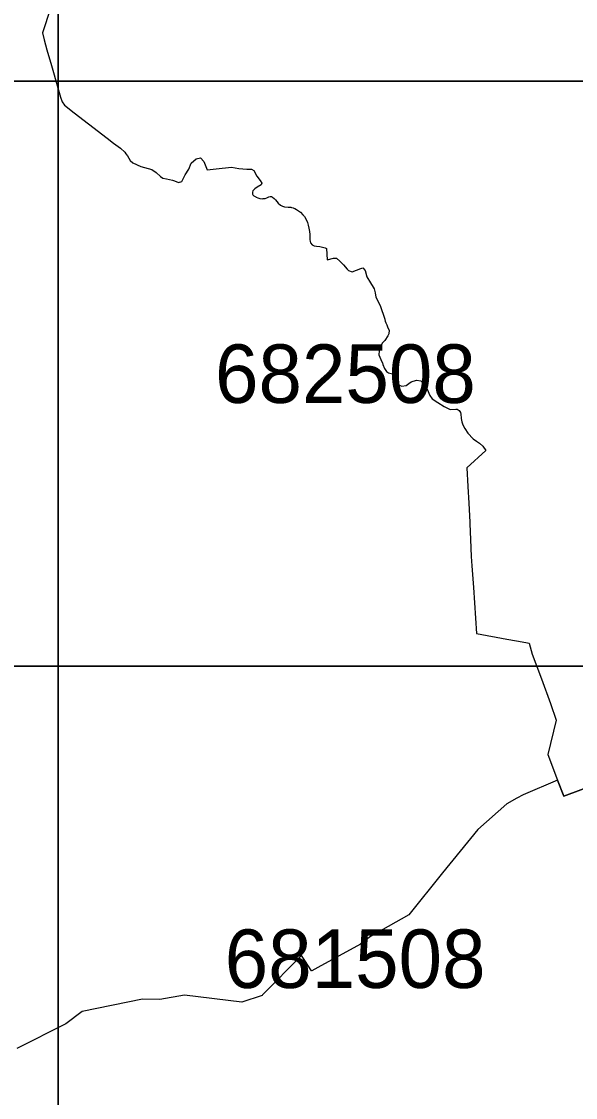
# Model space of a CAD drawing. Extents: x 25485000 to 25520000, y 6656775 to 6690000.
# Drawn here: x 25507937 to 25508885, y 6681263 to 6683102 of the extents above; entities that cross this region are included whole.
import ezdxf

# ---------------------------------------------------------------- set-up
doc = ezdxf.new("R2010")
doc.units = 0
doc.layers.add('Level 63', color=7, linetype='Continuous')

msp = doc.modelspace()

# ---------------------------------------------------------------- linework, layer by layer
at = {"layer": 'Level 63'}
for points in [[(25507000, 6683000), (25508000, 6683000), (25508000, 6684000), (25507000, 6684000)], [(25508000, 6683000), (25509000, 6683000), (25509000, 6684000), (25508000, 6684000)], [(25507000, 6682000), (25508000, 6682000), (25508000, 6683000), (25507000, 6683000)], [(25508000, 6682000), (25509000, 6682000), (25509000, 6683000), (25508000, 6683000)], [(25507000, 6681000), (25508000, 6681000), (25508000, 6682000), (25507000, 6682000)], [(25508000, 6681000), (25509000, 6681000), (25509000, 6682000), (25508000, 6682000)]]:
    msp.add_lwpolyline(points, close=True, dxfattribs=at)
for points in [[(25507986.9, 6683124.1), (25507973.1, 6683082.6), (25507976.3, 6683070.6), (25507981, 6683053.8), (25507988.6, 6683027), (25507999.4, 6682988.8), (25508004, 6682972.4), (25508007, 6682964.7), (25508011.2, 6682959), (25508027.8, 6682945.8), (25508052, 6682927.3), (25508083.9, 6682902.4), (25508094.7, 6682894.3), (25508106.7, 6682885.3), (25508114, 6682878.7), (25508116.2, 6682875.9), (25508119, 6682872.4), (25508123.5, 6682864.4), (25508127.8, 6682860.2), (25508141.6, 6682854.4), (25508160.6, 6682848.8), (25508167.8, 6682843.8), (25508175.1, 6682837.3), (25508179.5, 6682834.4), (25508185.7, 6682833.2), (25508195.8, 6682830.9), (25508199.4, 6682829.4), (25508205.8, 6682826.8), (25508211.5, 6682828.6), (25508217.5, 6682840), (25508223.9, 6682849.3), (25508227.9, 6682860), (25508236.5, 6682867.5), (25508243.4, 6682869.1), (25508249.6, 6682862.5), (25508255, 6682848.6), (25508270.6, 6682849.9), (25508296.7, 6682853), (25508309.4, 6682850.8), (25508323.2, 6682849.6), (25508330.9, 6682849.4), (25508334.8, 6682847.1), (25508340.3, 6682837.4), (25508345.6, 6682830.2), (25508348.8, 6682825.9), (25508347.3, 6682822.8), (25508340.7, 6682818.6), (25508336.5, 6682816), (25508333.3, 6682812.3), (25508332.6, 6682810), (25508332.4, 6682808.1), (25508332.6, 6682806.7), (25508333, 6682805.7), (25508335, 6682804), (25508338.3, 6682802.1), (25508339.1, 6682801.6), (25508342, 6682800.3), (25508345.4, 6682799.4), (25508350.2, 6682799.1), (25508350.9, 6682799.2), (25508354.2, 6682799.4), (25508357.3, 6682800.5), (25508360.8, 6682802.4), (25508362.9, 6682803), (25508365.1, 6682802.7), (25508367.1, 6682801.9), (25508369.7, 6682799.6), (25508372.1, 6682796.9), (25508374.1, 6682794.3), (25508376.8, 6682791.2), (25508380.3, 6682788.1), (25508383.9, 6682786.1), (25508387.5, 6682785.4), (25508393.6, 6682784.6), (25508394.9, 6682784.6), (25508398.2, 6682784.5), (25508399.6, 6682784.1), (25508402.2, 6682783.5), (25508403.2, 6682783.1), (25508405.1, 6682782.2), (25508408.1, 6682780.6), (25508411.5, 6682778.5), (25508414.6, 6682776.1), (25508419, 6682771.7), (25508421.7, 6682768.4), (25508424.4, 6682763.3), (25508426.5, 6682758.5), (25508428, 6682753.7), (25508429.2, 6682748.5), (25508430.1, 6682743.2), (25508430.7, 6682737.9), (25508430.9, 6682729.2), (25508431.2, 6682726.2), (25508431.8, 6682723.5), (25508434.9, 6682720.3), (25508438.2, 6682718.6), (25508441.9, 6682717.8), (25508447.8, 6682717.2), (25508457, 6682714.9), (25508459.1, 6682713.9), (25508460.4, 6682694.7), (25508471.3, 6682697.3), (25508476.2, 6682697.6), (25508482.2, 6682692.5), (25508488.1, 6682686), (25508494.6, 6682678.9), (25508496.8, 6682676.5), (25508503.2, 6682674.3), (25508518.2, 6682680), (25508521.6, 6682680.8), (25508525.5, 6682676.5), (25508528.2, 6682665.8), (25508534.7, 6682655), (25508539.1, 6682647.8), (25508540.7, 6682645.1), (25508542.7, 6682638.2), (25508543.5, 6682631), (25508551.1, 6682616.3), (25508558.8, 6682593.1), (25508559, 6682592.3), (25508559.5, 6682590.9), (25508559.9, 6682590), (25508561, 6682587), (25508562.3, 6682583.3), (25508564.3, 6682578.1), (25508566.4, 6682574.4), (25508566, 6682568.1), (25508564.2, 6682564.6), (25508558.8, 6682556.9), (25508554.6, 6682552.1), (25508549.3, 6682539), (25508548.8, 6682532.1), (25508552.2, 6682524.4), (25508554.6, 6682519.2), (25508555, 6682518.3), (25508555.8, 6682515.9), (25508558.3, 6682508.9), (25508561.7, 6682504), (25508565.4, 6682501.2), (25508572.3, 6682500), (25508574.4, 6682498.1), (25508580, 6682484), (25508582.5, 6682481.1), (25508588.2, 6682478.8), (25508595.3, 6682480), (25508599.9, 6682483), (25508604.1, 6682485.9), (25508613.4, 6682488.7), (25508620.5, 6682487.9), (25508626.1, 6682482.8), (25508631.5, 6682473.6), (25508635.9, 6682462.5), (25508639.9, 6682456.9), (25508650, 6682450.7), (25508660.8, 6682444.1), (25508671.1, 6682438.7), (25508680.6, 6682439.5), (25508683.1, 6682439.6), (25508686.5, 6682436.8), (25508688.5, 6682433.4), (25508688.9, 6682430.9), (25508689.2, 6682429.2), (25508689.6, 6682425.9), (25508689.9, 6682423.2), (25508690.7, 6682417.7), (25508692.6, 6682412.4), (25508695.9, 6682406.4), (25508701.3, 6682398.3), (25508710.1, 6682388.4), (25508715.7, 6682384.6), (25508720.9, 6682381.5), (25508726.9, 6682375.9), (25508731.8, 6682368.9), (25508699.2, 6682338.8), (25508701.1, 6682307.4), (25508702.8, 6682278.9), (25508704.3, 6682245.9), (25508704.4, 6682243.3), (25508705.7, 6682216.7), (25508707, 6682187.6), (25508708.1, 6682171.5), (25508710.6, 6682134.6), (25508716.1, 6682056.1), (25508767.8, 6682046.4), (25508784.6, 6682043.2), (25508800.2, 6682040.6), (25508805.9, 6682039.6), (25508811.4, 6682020.4), (25508827.1, 6681978.4), (25508842.4, 6681936.1), (25508852.4, 6681907.8), (25508837.8, 6681849.3), (25508854.4, 6681805.3), (25508865.6, 6681777.9), (25508919.2, 6681797.5)], [(25508919.2, 6681797.5), (25508865.6, 6681777.9), (25508854.4, 6681805.3), (25508795.6, 6681780.1), (25508785, 6681774.3), (25508768.1, 6681764.9), (25508718.3, 6681720.9), (25508657.7, 6681646.6), (25508600.4, 6681575.1), (25508564.6, 6681554.9), (25508534.8, 6681538.1), (25508517.5, 6681525.1), (25508444.7, 6681484.9), (25508434.1, 6681479), (25508433.4, 6681479), (25508422, 6681496.9), (25508417.6, 6681503.9), (25508416.6, 6681505.4), (25508349.8, 6681438), (25508349, 6681437.1), (25508314.4, 6681425.8), (25508216.5, 6681437.6), (25508174, 6681430), (25508144.6, 6681430.7), (25508041.2, 6681409.7), (25508013.4, 6681388.6), (25507929.6, 6681346.4)]]:
    msp.add_lwpolyline(points, dxfattribs=at)

# ---------------------------------------------------------------- texts
for s, p in [('682508', (25508268.5, 6682450)), ('681508', (25508285.1, 6681450))]:
    msp.add_text(s, height=100, dxfattribs=at).set_placement(p)

doc.saveas('drawing.dxf')
